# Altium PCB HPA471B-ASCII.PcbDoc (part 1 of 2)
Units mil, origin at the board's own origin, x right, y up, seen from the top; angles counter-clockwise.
Board outline 1305 x 1105 mil, 2 copper layers (Top Layer, Bottom Layer); 47 components, 32 nets, 115 pads, 21 vias.
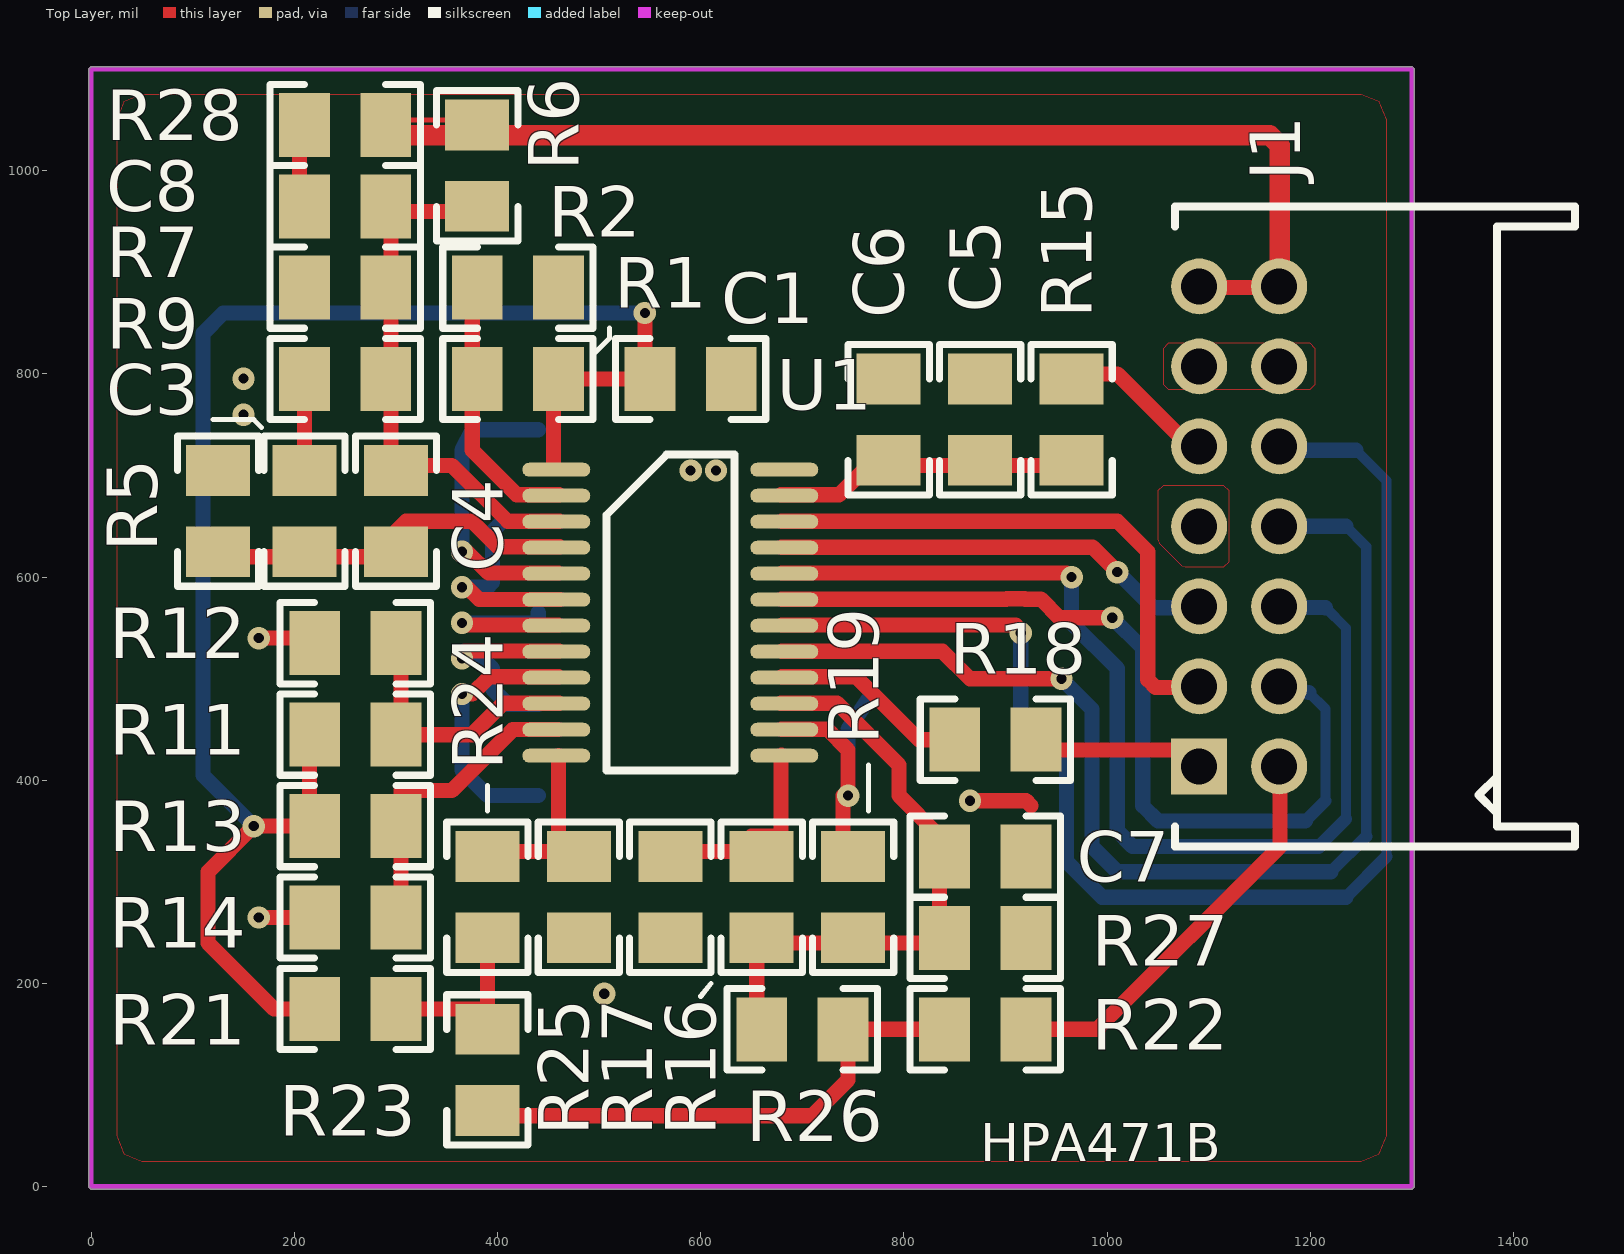
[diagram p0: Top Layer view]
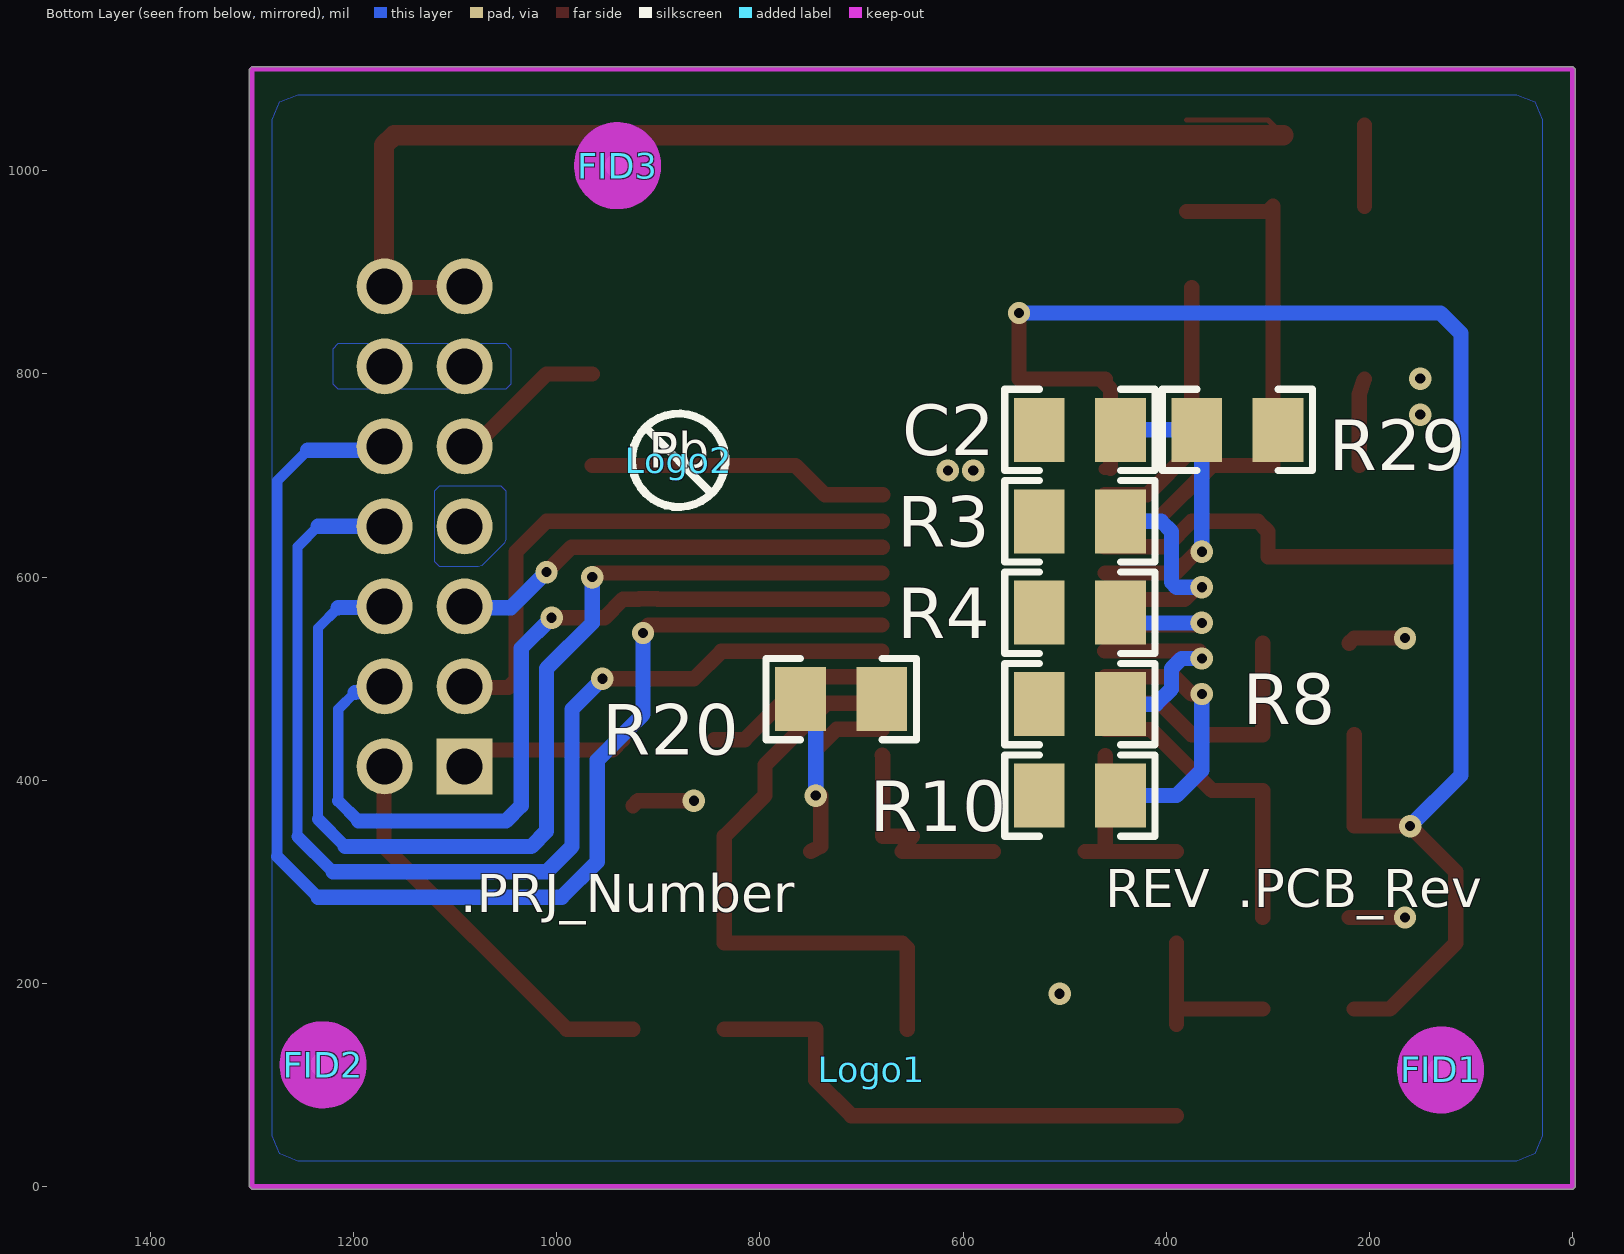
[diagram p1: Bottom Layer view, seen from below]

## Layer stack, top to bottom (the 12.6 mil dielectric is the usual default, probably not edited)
Top Layer: signal copper 2.8
Dielectric: core 12.6, FR-4, Dk 4.8
Bottom Layer: signal copper 2.8

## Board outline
-2.5,0 0,-2.5 1300,-2.5 1302.5,0 1302.5,1100 1300,1102.5 0,1102.5 -2.5,1100

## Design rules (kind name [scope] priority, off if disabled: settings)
AcuteAngle [All] p0: scope1count=1 scope1_0_kind=Board scope1_0_value=Board scope2count=1 scope2_0_kind=Board scope2_0_value=Board commentlength=0 minimum=4.50000000000000E+0001
AcuteAngle [All] p1: minimum=4.50000000000000E+0001 checktracksonly=TRUE
AssemblyTestPointUsage [All] p0: scope1count=1 scope1_0_kind=Board scope1_0_value=Board scope2count=1 scope2_0_kind=Board scope2_0_value=Board commentlength=0
AssemblyTestPointUsage [All] p1: valid=2
AssemblyTestpoint [All] p0: scope1count=1 scope1_0_kind=Board scope1_0_value=Board scope2count=1 scope2_0_kind=Board scope2_0_value=Board commentlength=0
Clearance Clearance_Poly [All] p0 off: scope1count=1 scope1_0_kind=Board scope1_0_value=Board scope2count=1 scope2_0_kind=Board scope2_0_value=Board commentlength=48 gap=12 // Protel DXP Scope 1 Expression Was: InPolygon
Clearance Clearance_BoardEdge_Poly [All] p0 off: scope1count=1 scope1_0_kind=Board scope1_0_value=Board scope2count=1 scope2_0_kind=Board scope2_0_value=Board commentlength=48 gap=19.68 // Protel DXP Scope 2 Expression Was: IsKeepOut
Clearance Clearance_BoardEdge [All] p0 off: scope1count=1 scope1_0_kind=Board scope1_0_value=Board scope2count=1 scope2_0_kind=Board scope2_0_value=Board commentlength=48 gap=19.68 // Protel DXP Scope 2 Expression Was: IsKeepout
Clearance Clearance_ALL [All] p0: scope1count=1 scope1_0_kind=Board scope1_0_value=Board scope2count=1 scope2_0_kind=Board scope2_0_value=Board commentlength=0 gap=8
Clearance Clearance_Poly [InPolygon] p1: gap=12
Clearance Clearance_BoardEdge_Poly [OnCopper and InPoly vs IsKeepOut] p2: gap=19.68
Clearance Clearance_BoardEdge [OnCopper and Not InComponentClass('Logo') and not InComponentClass('FiducialMark') and not InRegion(1000,500,4000,800) and Not IsKeepout vs IsKeepout] p3 off: gap=19.68
Clearance Clearance_ALL [All] p4: gap=8
ComponentClearance ComponentClearance_Logo [All] p0: scope1count=1 scope1_0_kind=ComponentClass scope1_0_value=Logo scope2count=1 scope2_0_kind=Board scope2_0_value=Board commentlength=0 gap=3.94 collisioncheckmode=3
ComponentClearance ComponentClearance_ScrewToNut [All] p0 off: scope1count=1 scope1_0_kind=Board scope1_0_value=Board scope2count=1 scope2_0_kind=Board scope2_0_value=Board commentlength=71 gap=0 collisioncheckmode=3 // Protel DXP Scope 2 Expression Was: (HasFootprint('Keystone_1902C'))
ComponentClearance ComponentClearance_MountingHoles [All] p0: scope1count=1 scope1_0_kind=ComponentClass scope1_0_value="Mounting Holes" scope2count=1 scope2_0_kind=Board scope2_0_value=Board commentlength=0 gap=19.68 collisioncheckmode=3
ComponentClearance ComponentClearance_SmallPassives [All] p0 off: scope1count=1 scope1_0_kind=Board scope1_0_value=Board scope2count=1 scope2_0_kind=Board scope2_0_value=Board commentlength=508 gap=7.87 collisioncheckmode=3 // Protel DXP Scope 2 Expression Was: HasFootprint('0201*') or HasFootprint('0402*') or HasFootprint('0508') or HasFootprint('0603*') or HasFootprint('0612') or HasFootprint('0805*') or HasFootprint('0815*') or HasFootprint('0830*') or HasFootprint('1206*') or HasFootprint('1210*') or HasFootprint('1808*') or HasFootprint('1812*') or HasFootprint('1825*') or HasFootprint('2010*') or HasFootprint('2220*') or HasFootprint('2225*') or HasFootprint('2512*') or HasFootprint('2728*') or HasFootprint('3518*')
ComponentClearance ComponentClearance_THtoSMT [All] p0 off: scope1count=1 scope1_0_kind=Board scope1_0_value=Board scope2count=1 scope2_0_kind=Board scope2_0_value=Board commentlength=53 gap=7.87 collisioncheckmode=3 // Protel DXP Scope 2 Expression Was: IsSMTComponent
ComponentClearance ComponentClearance_THtoTH [All] p0 off: scope1count=1 scope1_0_kind=Board scope1_0_value=Board scope2count=1 scope2_0_kind=Board scope2_0_value=Board commentlength=54 gap=7.87 collisioncheckmode=3 // Protel DXP Scope 2 Expression Was: IsThruComponent
ComponentClearance [All] p0: scope1count=1 scope1_0_kind=Board scope1_0_value=Board scope2count=1 scope2_0_kind=Board scope2_0_value=Board commentlength=0 gap=0 collisioncheckmode=3
ComponentClearance ComponentClearance_Logo [InComponentClass(Logo)] p1: gap=3.94 collisioncheckmode=3 verticalgap=27.56 showdistances=FALSE
ComponentClearance ComponentClearance_ScrewToNut [(HasFootprint('NY PMS 440 0025 PH')) vs (HasFootprint('Keystone_1902C'))] p2: gap=0 collisioncheckmode=3 verticalgap=0 showdistances=FALSE
ComponentClearance ComponentClearance_MountingHoles [InComponentClass('Mounting Holes')] p3: gap=19.68 collisioncheckmode=3 verticalgap=27.56 showdistances=FALSE
ComponentClearance ComponentClearance_SmallPassives [HasFootprint('0201*') or HasFootprint('0402*') or HasFootprint('0508') or HasFootprint('0603*') or HasFootprint('0612') or HasFootprint('0805*') or HasFootprint('0815*') or HasFootprint('0830*') or HasFootprint('1206*') or HasFootprint('1210*') or HasFootprint('1808*') or HasFootprint('1812*') or HasFootprint('1825*') or HasFootprint('2010*') or HasFootprint('2220*') or HasFootprint('2225*') or HasFootprint('2512*') or HasFootprint('2728*') or HasFootprint('3518*') vs HasFootprint('0201*') or HasFootprint('0402*') or HasFootprint('0508') or HasFootprint('0603*') or HasFootprint('0612') or HasFootprint('0805*') or HasFootprint('0815*') or HasFootprint('0830*') or HasFootprint('1206*') or HasFootprint('1210*') or HasFootprint('1808*') or HasFootprint('1812*') or HasFootprint('1825*') or HasFootprint('2010*') or HasFootprint('2220*') or HasFootprint('2225*') or HasFootprint('2512*') or HasFootprint('2728*') or HasFootprint('3518*')] p4: gap=7.87 collisioncheckmode=3 verticalgap=10 showdistances=FALSE
ComponentClearance ComponentClearance_THtoSMT [IsThruComponent vs IsSMTComponent] p5 off: gap=7.87 collisioncheckmode=3 verticalgap=27.56 showdistances=FALSE
ComponentClearance ComponentClearance_THtoTH [IsThruComponent vs IsThruComponent] p6 off: gap=7.87 collisioncheckmode=3 verticalgap=27.56 showdistances=FALSE
ComponentClearance [All] p7: gap=0 collisioncheckmode=3 verticalgap=0 showdistances=FALSE
DiffPairsRouting [All] p0: scope1count=1 scope1_0_kind=Board scope1_0_value=Board scope2count=1 scope2_0_kind=Board scope2_0_value=Board commentlength=0
DiffPairsRouting [All] p1: maxlimit=100 minlimit=10 mostfreqgap=10 maxuncoupledlength=1000
FabricationTestPointUsage TestPointUsage [All] p0: scope1count=1 scope1_0_kind=Board scope1_0_value=Board scope2count=1 scope2_0_kind=Board scope2_0_value=Board commentlength=0 valid=2 allowmultiple=FALSE
FabricationTestPointUsage TestPointUsage [All] p1: valid=2 allowmultiple=FALSE
FabricationTestpoint Testpoint [All] p0: scope1count=1 scope1_0_kind=Board scope1_0_value=Board scope2count=1 scope2_0_kind=Board scope2_0_value=Board commentlength=0 side=3 testpointundercomponent=TRUE minsize=40 maxsize=100 preferedsize=60 minholesize=0 maxholesize=40 preferedholesize=32 testpointgrid=1
FabricationTestpoint Testpoint [All] p1: side=3 testpointundercomponent=TRUE minsize=40 maxsize=100 preferedsize=60 minholesize=0 maxholesize=40 preferedholesize=32 testpointgrid=1 allowsidetop=TRUE allowsidebottom=TRUE usegrid=TRUE gridtolerance=0.01
FanoutControl Fanout_LCC [All] p0 off: scope1count=1 scope1_0_kind=Board scope1_0_value=Board scope2count=1 scope2_0_kind=Board scope2_0_value=Board commentlength=69 // Protel DXP Scope 1 Expression Was: IsLCC   Fanout_LCC (Default Rule)
FanoutControl Fanout_BGA [All] p0 off: scope1count=1 scope1_0_kind=Board scope1_0_value=Board scope2count=1 scope2_0_kind=Board scope2_0_value=Board commentlength=69 // Protel DXP Scope 1 Expression Was: IsBGA   Fanout_BGA (Default Rule)
FanoutControl Fanout_SOIC [All] p0 off: scope1count=1 scope1_0_kind=Board scope1_0_value=Board scope2count=1 scope2_0_kind=Board scope2_0_value=Board commentlength=71 // Protel DXP Scope 1 Expression Was: IsSOIC   Fanout_SOIC (Default Rule)
FanoutControl Fanout_Default [All] p0: scope1count=1 scope1_0_kind=Board scope1_0_value=Board scope2count=1 scope2_0_kind=Board scope2_0_value=Board commentlength=30 // Fanout_Default (Default Rule)
FanoutControl Fanout_Small [All] p0 off: scope1count=1 scope1_0_kind=Board scope1_0_value=Board scope2count=1 scope2_0_kind=Board scope2_0_value=Board commentlength=84 // Protel DXP Scope 1 Expression Was: (CompPinCount < 5)   Fanout_Small (Default Rule)
FanoutControl Fanout_LCC [IsLCC] p1: bgadir=Out bgaviamode=Centered fanoutstyle=Auto fanoutdirection=Alternating viagrid=1 // Fanout_LCC (Default Rule)
FanoutControl Fanout_BGA [IsBGA] p2: bgadir=Out bgaviamode=Centered fanoutstyle=Auto fanoutdirection=Alternating viagrid=1 // Fanout_BGA (Default Rule)
FanoutControl Fanout_Default [All] p4: bgadir=Out bgaviamode=Centered fanoutstyle=Auto fanoutdirection=Alternating viagrid=1 // Fanout_Default (Default Rule)
FanoutControl Fanout_Small [(CompPinCount < 5)] p5: bgadir=Out bgaviamode=Centered fanoutstyle=Auto fanoutdirection=OutThenIn viagrid=1 // Fanout_Small (Default Rule)
Height "Height Bottom" [All] p0 off: scope1count=1 scope1_0_kind=Board scope1_0_value=Board scope2count=1 scope2_0_kind=Board scope2_0_value=Board commentlength=64 // Protel DXP Scope 1 Expression Was: (OnLayer('Bottom Layer'))
Height Height_top [All] p0 off: scope1count=1 scope1_0_kind=Board scope1_0_value=Board scope2count=1 scope2_0_kind=Board scope2_0_value=Board commentlength=61 // Protel DXP Scope 1 Expression Was: (OnLayer('Top Layer'))
Height "Height Bottom" [(OnLayer('Bottom Layer'))] p1: minheight=0 maxheight=1000 prefheight=500
Height Height_top [(OnLayer('Top Layer'))] p2: minheight=0 maxheight=1750 prefheight=1750
HoleSize [All] p0: scope1count=1 scope1_0_kind=Board scope1_0_value=Board scope2count=1 scope2_0_kind=Board scope2_0_value=Board commentlength=0 absolutevalues=TRUE maxlimit=275.59 minlimit=8 maxpercent=80.000 minpercent=20.000
HoleSize [All] p1: absolutevalues=TRUE maxlimit=275.59 minlimit=8 maxpercent=80.000 minpercent=20.000
HoleToHoleClearance [All] p0: scope1count=1 scope1_0_kind=Board scope1_0_value=Board scope2count=1 scope2_0_kind=Board scope2_0_value=Board commentlength=0
LayerPairs [All] p0: scope1count=1 scope1_0_kind=Board scope1_0_value=Board scope2count=1 scope2_0_kind=Board scope2_0_value=Board commentlength=0 enforce=TRUE
MinimumAnnularRing [All] p0: scope1count=1 scope1_0_kind=Board scope1_0_value=Board scope2count=1 scope2_0_kind=Board scope2_0_value=Board commentlength=0 minimumring=6
MinimumAnnularRing [All] p1: minimumring=6
MinimumSolderMaskSliver MinimumSolderMaskSliver_Logo [All] p0: scope1count=1 scope1_0_kind=ComponentClass scope1_0_value=Logo scope2count=1 scope2_0_kind=ComponentClass scope2_0_value=Logo commentlength=0
MinimumSolderMaskSliver [All] p0: scope1count=1 scope1_0_kind=Board scope1_0_value=Board scope2count=1 scope2_0_kind=Board scope2_0_value=Board commentlength=0
MinimumSolderMaskSliver MinimumSolderMaskSliver_Logo [InComponentClass('Logo') vs InComponentClass('Logo')] p1: minsoldermaskwidth=0.7
MinimumSolderMaskSliver [All] p2: minsoldermaskwidth=4
NetAntennae [All] p0: scope1count=1 scope1_0_kind=Board scope1_0_value=Board scope2count=1 scope2_0_kind=Board scope2_0_value=Board commentlength=0
PasteMaskExpansion [All] p0: scope1count=1 scope1_0_kind=Board scope1_0_value=Board scope2count=1 scope2_0_kind=Board scope2_0_value=Board commentlength=0 expansion=0
PlaneClearance [All] p0: scope1count=1 scope1_0_kind=Board scope1_0_value=Board scope2count=1 scope2_0_kind=Board scope2_0_value=Board commentlength=0 clearance=20
PlaneConnect [All] p0: scope1count=1 scope1_0_kind=Board scope1_0_value=Board scope2count=1 scope2_0_kind=Board scope2_0_value=Board commentlength=0 planeconnectstyle=Relief reliefexpansion=10 reliefentries=4 reliefconductorwidth=10 reliefairgap=10
PlaneConnect [All] p1: planeconnectstyle=Relief reliefexpansion=10 reliefentries=4 reliefconductorwidth=10 reliefairgap=10
PolygonConnect PolygonConnect_23 [All] p0 off: scope1count=1 scope1_0_kind=Board scope1_0_value=Board scope2count=1 scope2_0_kind=Board scope2_0_value=Board commentlength=80 connectstyle=Direct reliefconductorwidth=10 reliefentries=4 polygonreliefangle="90 Angle" // Protel DXP Scope 2 Expression Was: IsNamedPolygon('Top Layer, Top-PWRGND 4')
PolygonConnect PolygonConnect_22 [All] p0 off: scope1count=1 scope1_0_kind=Board scope1_0_value=Board scope2count=1 scope2_0_kind=Board scope2_0_value=Board commentlength=80 connectstyle=Direct reliefconductorwidth=10 reliefentries=4 polygonreliefangle="90 Angle" // Protel DXP Scope 2 Expression Was: IsNamedPolygon('Top Layer, Top-PWRGND 4')
PolygonConnect PolygonConnect_21 [All] p0 off: scope1count=1 scope1_0_kind=Board scope1_0_value=Board scope2count=1 scope2_0_kind=Board scope2_0_value=Board commentlength=80 connectstyle=Direct reliefconductorwidth=10 reliefentries=4 polygonreliefangle="90 Angle" // Protel DXP Scope 2 Expression Was: IsNamedPolygon('Top Layer, Top-PWRGND 2')
PolygonConnect PolygonConnect_20 [All] p0 off: scope1count=1 scope1_0_kind=Board scope1_0_value=Board scope2count=1 scope2_0_kind=Board scope2_0_value=Board commentlength=80 connectstyle=Direct reliefconductorwidth=10 reliefentries=4 polygonreliefangle="90 Angle" // Protel DXP Scope 2 Expression Was: IsNamedPolygon('Top Layer, Top-PWRGND 3')
PolygonConnect PolygonConnect_19 [All] p0 off: scope1count=1 scope1_0_kind=Board scope1_0_value=Board scope2count=1 scope2_0_kind=Board scope2_0_value=Board commentlength=80 connectstyle=Direct reliefconductorwidth=10 reliefentries=4 polygonreliefangle="90 Angle" // Protel DXP Scope 2 Expression Was: IsNamedPolygon('Top Layer, Top-PWRGND 4')
PolygonConnect PolygonConnect_18 [All] p0 off: scope1count=1 scope1_0_kind=Board scope1_0_value=Board scope2count=1 scope2_0_kind=Board scope2_0_value=Board commentlength=75 connectstyle=Direct reliefconductorwidth=10 reliefentries=4 polygonreliefangle="90 Angle" // Protel DXP Scope 2 Expression Was: IsNamedPolygon('Top Layer, Top-GND')
PolygonConnect PolygonConnect_17 [All] p0 off: scope1count=1 scope1_0_kind=Board scope1_0_value=Board scope2count=1 scope2_0_kind=Board scope2_0_value=Board commentlength=77 connectstyle=Direct reliefconductorwidth=10 reliefentries=4 polygonreliefangle="90 Angle" // Protel DXP Scope 2 Expression Was: IsNamedPolygon('Top Layer, Top-GND 1')
PolygonConnect PolygonConnect_16 [All] p0 off: scope1count=1 scope1_0_kind=Board scope1_0_value=Board scope2count=1 scope2_0_kind=Board scope2_0_value=Board commentlength=77 connectstyle=Direct reliefconductorwidth=10 reliefentries=4 polygonreliefangle="90 Angle" // Protel DXP Scope 2 Expression Was: IsNamedPolygon('Top Layer, Top-GND 2')
PolygonConnect PolygonConnect_15 [All] p0 off: scope1count=1 scope1_0_kind=Board scope1_0_value=Board scope2count=1 scope2_0_kind=Board scope2_0_value=Board commentlength=80 connectstyle=Direct reliefconductorwidth=10 reliefentries=4 polygonreliefangle="90 Angle" // Protel DXP Scope 2 Expression Was: IsNamedPolygon('Top Layer, Top-NET00002')
PolygonConnect PolygonConnect_14 [All] p0 off: scope1count=1 scope1_0_kind=Board scope1_0_value=Board scope2count=1 scope2_0_kind=Board scope2_0_value=Board commentlength=80 connectstyle=Direct reliefconductorwidth=10 reliefentries=4 polygonreliefangle="90 Angle" // Protel DXP Scope 2 Expression Was: IsNamedPolygon('Top Layer, Top-NET00003')
PolygonConnect PolygonConnect_13 [All] p0 off: scope1count=1 scope1_0_kind=Board scope1_0_value=Board scope2count=1 scope2_0_kind=Board scope2_0_value=Board commentlength=80 connectstyle=Direct reliefconductorwidth=10 reliefentries=4 polygonreliefangle="90 Angle" // Protel DXP Scope 2 Expression Was: IsNamedPolygon('Top Layer, Top-NET00003')
PolygonConnect PolygonConnect_12 [All] p0 off: scope1count=1 scope1_0_kind=Board scope1_0_value=Board scope2count=1 scope2_0_kind=Board scope2_0_value=Board commentlength=80 connectstyle=Direct reliefconductorwidth=10 reliefentries=4 polygonreliefangle="90 Angle" // Protel DXP Scope 2 Expression Was: IsNamedPolygon('Top Layer, Top-NET00007')
PolygonConnect PolygonConnect_11 [All] p0 off: scope1count=1 scope1_0_kind=Board scope1_0_value=Board scope2count=1 scope2_0_kind=Board scope2_0_value=Board commentlength=80 connectstyle=Direct reliefconductorwidth=10 reliefentries=4 polygonreliefangle="90 Angle" // Protel DXP Scope 2 Expression Was: IsNamedPolygon('Top Layer, Top-NET00016')
PolygonConnect PolygonConnect_10 [All] p0 off: scope1count=1 scope1_0_kind=Board scope1_0_value=Board scope2count=1 scope2_0_kind=Board scope2_0_value=Board commentlength=80 connectstyle=Direct reliefconductorwidth=10 reliefentries=4 polygonreliefangle="90 Angle" // Protel DXP Scope 2 Expression Was: IsNamedPolygon('Top Layer, Top-NET00025')
PolygonConnect PolygonConnect_9 [All] p0 off: scope1count=1 scope1_0_kind=Board scope1_0_value=Board scope2count=1 scope2_0_kind=Board scope2_0_value=Board commentlength=82 connectstyle=Direct reliefconductorwidth=10 reliefentries=4 polygonreliefangle="90 Angle" // Protel DXP Scope 2 Expression Was: IsNamedPolygon('Top Layer, Top-NET00025 1')
PolygonConnect PolygonConnect_8 [All] p0 off: scope1count=1 scope1_0_kind=Board scope1_0_value=Board scope2count=1 scope2_0_kind=Board scope2_0_value=Board commentlength=78 connectstyle=Direct reliefconductorwidth=10 reliefentries=4 polygonreliefangle="90 Angle" // Protel DXP Scope 2 Expression Was: IsNamedPolygon('Top Layer, Top-No Net')
PolygonConnect PolygonConnect_7 [All] p0 off: scope1count=1 scope1_0_kind=Board scope1_0_value=Board scope2count=1 scope2_0_kind=Board scope2_0_value=Board commentlength=78 connectstyle=Direct reliefconductorwidth=10 reliefentries=4 polygonreliefangle="90 Angle" // Protel DXP Scope 2 Expression Was: IsNamedPolygon('Top Layer, Top-PWRGND')
PolygonConnect PolygonConnect_6 [All] p0 off: scope1count=1 scope1_0_kind=Board scope1_0_value=Board scope2count=1 scope2_0_kind=Board scope2_0_value=Board commentlength=80 connectstyle=Direct reliefconductorwidth=10 reliefentries=4 polygonreliefangle="90 Angle" // Protel DXP Scope 2 Expression Was: IsNamedPolygon('Top Layer, Top-PWRGND 1')
PolygonConnect PolygonConnect_5 [All] p0 off: scope1count=1 scope1_0_kind=Board scope1_0_value=Board scope2count=1 scope2_0_kind=Board scope2_0_value=Board commentlength=80 connectstyle=Direct reliefconductorwidth=10 reliefentries=4 polygonreliefangle="90 Angle" // Protel DXP Scope 2 Expression Was: IsNamedPolygon('Top Layer, Top-PWRGND 2')
PolygonConnect PolygonConnect_4 [All] p0 off: scope1count=1 scope1_0_kind=Board scope1_0_value=Board scope2count=1 scope2_0_kind=Board scope2_0_value=Board commentlength=80 connectstyle=Direct reliefconductorwidth=10 reliefentries=4 polygonreliefangle="90 Angle" // Protel DXP Scope 2 Expression Was: IsNamedPolygon('Top Layer, Top-PWRGND 3')
PolygonConnect PolygonConnect_3 [All] p0 off: scope1count=1 scope1_0_kind=Board scope1_0_value=Board scope2count=1 scope2_0_kind=Board scope2_0_value=Board commentlength=80 connectstyle=Direct reliefconductorwidth=10 reliefentries=4 polygonreliefangle="90 Angle" // Protel DXP Scope 2 Expression Was: IsNamedPolygon('Top Layer, Top-PWRGND 4')
PolygonConnect PolygonConnect_2 [All] p0 off: scope1count=1 scope1_0_kind=Board scope1_0_value=Board scope2count=1 scope2_0_kind=Board scope2_0_value=Board commentlength=126 connectstyle=Direct reliefconductorwidth=10 reliefentries=4 polygonreliefangle="90 Angle" // Protel DXP Scope 2 Expression Was: IsNamedPolygon('Top Layer, Top-PWRGND 3') Or  IsNamedPolygon('Top Layer, Top-PWRGND 4')
PolygonConnect PolygonConnect_1 [All] p0 off: scope1count=1 scope1_0_kind=Board scope1_0_value=Board scope2count=1 scope2_0_kind=Board scope2_0_value=Board commentlength=1642 connectstyle=Direct reliefconductorwidth=10 reliefentries=4 polygonreliefangle="90 Angle" // Protel DXP Scope 2 Expression Was: IsNamedPolygon('Top Layer, Top-PWRGND 2') Or  IsNamedPolygon('Bottom Layer, Bottom-GND') Or  IsNamedPolygon('Bottom Layer, Bottom-NET00038') Or  IsNamedPolygon('Bottom Layer, Bottom-NET00006') Or  IsNamedPolygon('Bottom Layer, Bottom-NET00003') Or  IsNamedPolygon('Bottom Layer, Bottom-NET00004 2') Or  IsNamedPolygon('Bottom Layer, Bottom-NET00020') Or  IsNamedPolygon('Bottom Layer, Bottom-GND 2') Or  IsNamedPolygon('Bottom Layer, Bottom-NET00004') Or  IsNamedPolygon('Bottom Layer, Bottom-PWRGND') Or  IsNamedPolygon('Bottom Layer, Bottom-NET00002 1') Or  IsNamedPolygon('Bottom Layer, Bottom-NET00013') Or  IsNamedPolygon('Bottom Layer, Bottom-NET00012') Or  IsNamedPolygon('Bottom Layer, Bottom-NET00004 3') Or  IsNamedPolygon('Bottom Layer, Bottom-NET00004 1') Or  IsNamedPolygon('Bottom Layer, Bottom-NET00016') Or  IsNamedPolygon('Bottom Layer, Bottom-GND 1') Or  IsNamedPolygon('Bottom Layer, Bottom-NET00025') Or  IsNamedPolygon('Bottom Layer, Bottom-NET00002') Or  IsNamedPolygon('Top Layer, Top-No Net') Or  IsNamedPolygon('Top Layer, Top-NET00016') Or  IsNamedPolygon('Top Layer, Top-NET00025 1') Or  IsNamedPolygon('Top Layer, Top-GND 2') Or  IsNamedPolygon('Top Layer, Top-PWRGND 3') Or  IsNamedPolygon('Top Layer, Top-PWRGND 4') Or  IsNamedPolygon('Top Layer, Top-NET00002') Or  IsNamedPolygon('Top Layer, Top-NET00007') Or  IsNamedPolygon('Top Layer, Top-GND 1') Or  IsNamedPolygon('Top Layer, Top-PWRGND 1') Or  IsNamedPolygon('Top Layer, Top-GND') Or  IsNamedPolygon('Top Layer, Top-NET00025') Or  IsNamedPolygon('Top Layer, Top-NET00003') Or  IsNamedPolygon('Top Layer, Top-PWRGND')
PolygonConnect [All] p0: scope1count=1 scope1_0_kind=Board scope1_0_value=Board scope2count=1 scope2_0_kind=Board scope2_0_value=Board commentlength=0 connectstyle=Relief reliefconductorwidth=10 reliefentries=4 polygonreliefangle="90 Angle"
PolygonConnect PolygonConnect_23 [All vs IsNamedPolygon('Top Layer, Top-PWRGND 4')] p1: connectstyle=Direct reliefconductorwidth=10 reliefentries=4 polygonreliefangle="90 Angle" airgapwidth=10
PolygonConnect PolygonConnect_22 [All vs IsNamedPolygon('Top Layer, Top-PWRGND 4')] p2: connectstyle=Direct reliefconductorwidth=10 reliefentries=4 polygonreliefangle="90 Angle" airgapwidth=10
PolygonConnect PolygonConnect_21 [All vs IsNamedPolygon('Top Layer, Top-PWRGND 2')] p3: connectstyle=Direct reliefconductorwidth=10 reliefentries=4 polygonreliefangle="90 Angle" airgapwidth=10
PolygonConnect PolygonConnect_20 [All vs IsNamedPolygon('Top Layer, Top-PWRGND 3')] p4: connectstyle=Direct reliefconductorwidth=10 reliefentries=4 polygonreliefangle="90 Angle" airgapwidth=10
PolygonConnect PolygonConnect_19 [All vs IsNamedPolygon('Top Layer, Top-PWRGND 4')] p5: connectstyle=Direct reliefconductorwidth=10 reliefentries=4 polygonreliefangle="90 Angle" airgapwidth=10
PolygonConnect PolygonConnect_18 [All vs IsNamedPolygon('Top Layer, Top-GND')] p6: connectstyle=Direct reliefconductorwidth=10 reliefentries=4 polygonreliefangle="90 Angle" airgapwidth=10
PolygonConnect PolygonConnect_17 [All vs IsNamedPolygon('Top Layer, Top-GND 1')] p7: connectstyle=Direct reliefconductorwidth=10 reliefentries=4 polygonreliefangle="90 Angle" airgapwidth=10
PolygonConnect PolygonConnect_16 [All vs IsNamedPolygon('Top Layer, Top-GND 2')] p8: connectstyle=Direct reliefconductorwidth=10 reliefentries=4 polygonreliefangle="90 Angle" airgapwidth=10
PolygonConnect PolygonConnect_15 [All vs IsNamedPolygon('Top Layer, Top-NET00002')] p9: connectstyle=Direct reliefconductorwidth=10 reliefentries=4 polygonreliefangle="90 Angle" airgapwidth=10
PolygonConnect PolygonConnect_14 [All vs IsNamedPolygon('Top Layer, Top-NET00003')] p10: connectstyle=Direct reliefconductorwidth=10 reliefentries=4 polygonreliefangle="90 Angle" airgapwidth=10
PolygonConnect PolygonConnect_13 [All vs IsNamedPolygon('Top Layer, Top-NET00003')] p11: connectstyle=Direct reliefconductorwidth=10 reliefentries=4 polygonreliefangle="90 Angle" airgapwidth=10
PolygonConnect PolygonConnect_12 [All vs IsNamedPolygon('Top Layer, Top-NET00007')] p12: connectstyle=Direct reliefconductorwidth=10 reliefentries=4 polygonreliefangle="90 Angle" airgapwidth=10
PolygonConnect PolygonConnect_11 [All vs IsNamedPolygon('Top Layer, Top-NET00016')] p13: connectstyle=Direct reliefconductorwidth=10 reliefentries=4 polygonreliefangle="90 Angle" airgapwidth=10
PolygonConnect PolygonConnect_10 [All vs IsNamedPolygon('Top Layer, Top-NET00025')] p14: connectstyle=Direct reliefconductorwidth=10 reliefentries=4 polygonreliefangle="90 Angle" airgapwidth=10
PolygonConnect PolygonConnect_9 [All vs IsNamedPolygon('Top Layer, Top-NET00025 1')] p15: connectstyle=Direct reliefconductorwidth=10 reliefentries=4 polygonreliefangle="90 Angle" airgapwidth=10
PolygonConnect PolygonConnect_8 [All vs IsNamedPolygon('Top Layer, Top-No Net')] p16: connectstyle=Direct reliefconductorwidth=10 reliefentries=4 polygonreliefangle="90 Angle" airgapwidth=10
PolygonConnect PolygonConnect_7 [All vs IsNamedPolygon('Top Layer, Top-PWRGND')] p17: connectstyle=Direct reliefconductorwidth=10 reliefentries=4 polygonreliefangle="90 Angle" airgapwidth=10
PolygonConnect PolygonConnect_6 [All vs IsNamedPolygon('Top Layer, Top-PWRGND 1')] p18: connectstyle=Direct reliefconductorwidth=10 reliefentries=4 polygonreliefangle="90 Angle" airgapwidth=10
PolygonConnect PolygonConnect_5 [All vs IsNamedPolygon('Top Layer, Top-PWRGND 2')] p19: connectstyle=Direct reliefconductorwidth=10 reliefentries=4 polygonreliefangle="90 Angle" airgapwidth=10
PolygonConnect PolygonConnect_4 [All vs IsNamedPolygon('Top Layer, Top-PWRGND 3')] p20: connectstyle=Direct reliefconductorwidth=10 reliefentries=4 polygonreliefangle="90 Angle" airgapwidth=10
PolygonConnect PolygonConnect_3 [All vs IsNamedPolygon('Top Layer, Top-PWRGND 4')] p21: connectstyle=Direct reliefconductorwidth=10 reliefentries=4 polygonreliefangle="90 Angle" airgapwidth=10
PolygonConnect PolygonConnect_2 [All vs IsNamedPolygon('Top Layer, Top-PWRGND 3') Or  IsNamedPolygon('Top Layer, Top-PWRGND 4')] p22: connectstyle=Direct reliefconductorwidth=10 reliefentries=4 polygonreliefangle="90 Angle" airgapwidth=10
PolygonConnect PolygonConnect_1 [All vs IsNamedPolygon('Top Layer, Top-PWRGND 2') Or  IsNamedPolygon('Bottom Layer, Bottom-GND') Or  IsNamedPolygon('Bottom Layer, Bottom-NET00038') Or  IsNamedPolygon('Bottom Layer, Bottom-NET00006') Or  IsNamedPolygon('Bottom Layer, Bottom-NET00003') Or  IsNamedPolygon('Bottom Layer, Bottom-NET00004 2') Or  IsNamedPolygon('Bottom Layer, Bottom-NET00020') Or  IsNamedPolygon('Bottom Layer, Bottom-GND 2') Or  IsNamedPolygon('Bottom Layer, Bottom-NET00004') Or  IsNamedPolygon('Bottom Layer, Bottom-PWRGND') Or  IsNamedPolygon('Bottom Layer, Bottom-NET00002 1') Or  IsNamedPolygon('Bottom Layer, Bottom-NET00013') Or  IsNamedPolygon('Bottom Layer, Bottom-NET00012') Or  IsNamedPolygon('Bottom Layer, Bottom-NET00004 3') Or  IsNamedPolygon('Bottom Layer, Bottom-NET00004 1') Or  IsNamedPolygon('Bottom Layer, Bottom-NET00016') Or  IsNamedPolygon('Bottom Layer, Bottom-GND 1') Or  IsNamedPolygon('Bottom Layer, Bottom-NET00025') Or  IsNamedPolygon('Bottom Layer, Bottom-NET00002') Or  IsNamedPolygon('Top Layer, Top-No Net') Or  IsNamedPolygon('Top Layer, Top-NET00016') Or  IsNamedPolygon('Top Layer, Top-NET00025 1') Or  IsNamedPolygon('Top Layer, Top-GND 2') Or  IsNamedPolygon('Top Layer, Top-PWRGND 3') Or  IsNamedPolygon('Top Layer, Top-PWRGND 4') Or  IsNamedPolygon('Top Layer, Top-NET00002') Or  IsNamedPolygon('Top Layer, Top-NET00007') Or  IsNamedPolygon('Top Layer, Top-GND 1') Or  IsNamedPolygon('Top Layer, Top-PWRGND 1') Or  IsNamedPolygon('Top Layer, Top-GND') Or  IsNamedPolygon('Top Layer, Top-NET00025') Or  IsNamedPolygon('Top Layer, Top-NET00003') Or  IsNamedPolygon('Top Layer, Top-PWRGND')] p23: connectstyle=Direct reliefconductorwidth=10 reliefentries=4 polygonreliefangle="90 Angle" airgapwidth=10
PolygonConnect [All] p24: connectstyle=Relief reliefconductorwidth=10 reliefentries=4 polygonreliefangle="90 Angle" airgapwidth=10
RoutingCorners [All] p0: scope1count=1 scope1_0_kind=Board scope1_0_value=Board scope2count=1 scope2_0_kind=Board scope2_0_value=Board commentlength=0 cornerstyle=45-Degree minsetback=100 maxsetback=100
RoutingLayers [All] p0: scope1count=1 scope1_0_kind=Board scope1_0_value=Board scope2count=1 scope2_0_kind=Board scope2_0_value=Board commentlength=0 top layer=Automatic bottom layer=Automatic
RoutingPriority [All] p0: scope1count=1 scope1_0_kind=Board scope1_0_value=Board scope2count=1 scope2_0_kind=Board scope2_0_value=Board commentlength=0
RoutingTopology [All] p0: scope1count=1 scope1_0_kind=Board scope1_0_value=Board scope2count=1 scope2_0_kind=Board scope2_0_value=Board commentlength=0 topology=Shortest
RoutingVias [All] p0: scope1count=1 scope1_0_kind=Board scope1_0_value=Board scope2count=1 scope2_0_kind=Board scope2_0_value=Board commentlength=0 holewidth=16 width=34 viastyle="Through Hole" minholewidth=6 minwidth=10 maxholewidth=40 maxwidth=65
RoutingVias [All] p1: holewidth=16 width=34 viastyle="Through Hole" minholewidth=6 minwidth=10 maxholewidth=40 maxwidth=65
SMDToCorner [All] p0 off: scope1count=1 scope1_0_kind=Board scope1_0_value=Board scope2count=1 scope2_0_kind=Board scope2_0_value=Board commentlength=0 distance=30000
SMDToCorner [All] p1 off: distance=30000
ShortCircuit [All] p0: scope1count=1 scope1_0_kind=Board scope1_0_value=Board scope2count=1 scope2_0_kind=Board scope2_0_value=Board commentlength=0 allowed=FALSE
SilkToSilkClearance [All] p0 off: scope1count=1 scope1_0_kind=Board scope1_0_value=Board scope2count=1 scope2_0_kind=Board scope2_0_value=Board commentlength=0
SilkToSilkClearance [All] p1 off: silktosilkclearance=4.5
SilkscreenOverComponentPads [All] p0 off: scope1count=1 scope1_0_kind=Board scope1_0_value=Board scope2count=1 scope2_0_kind=Board scope2_0_value=Board commentlength=0
SilkscreenOverComponentPads [All] p1 off: minsilkscreentomaskgap=5
SolderMaskExpansion [All] p0: scope1count=1 scope1_0_kind=Board scope1_0_value=Board scope2count=1 scope2_0_kind=Board scope2_0_value=Board commentlength=0 expansion=3
SolderMaskExpansion [All] p1: expansion=3
UnRoutedNet [All] p0: scope1count=1 scope1_0_kind=Board scope1_0_value=Board scope2count=1 scope2_0_kind=Board scope2_0_value=Board commentlength=0
Width [All] p0: scope1count=1 scope1_0_kind=Board scope1_0_value=Board scope2count=1 scope2_0_kind=Board scope2_0_value=Board commentlength=0 maxlimit=100 minlimit=10 preferedwidth=31.5
Width [All] p1: maxlimit=100 minlimit=10 preferedwidth=31.5 checkconnectedcopper=TRUE
13 further rules are at their usual default settings.

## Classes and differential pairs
component class HPA471B_Sht01: C1 C2 C3 C4 C5 C6 C7 C8 J1 R1 R2 R3 R4 R5 R6 R7 R8 R9 R10 R11 R12 R13 R14 R15 R16 R17 R18 R19 R20 R21 R22 R23 R24 R25 R26 R27 R28 R29 U1
component class HPA471B_Hardware: !PCB FID1 FID2 FID3 Logo1 Logo2 ZZ1 ZZ2 ZZ3

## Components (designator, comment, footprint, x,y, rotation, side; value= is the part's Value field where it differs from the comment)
C1 "08055C105KAT2A" 0805_HV 590,795 r180 top
C2 "C0805C154K5RACTU" 0805_HV 485,745 r180 bottom
C3 "08055C562KAT2A" 0805_HV 210,665 r90 top
C4 "08055C561KAT2A" 0805_HV 300,665 r90 top
C5 "08055C105KAT2A" 0805_HV 875,755 r270 top
C6 "08053C104KAT2A" 0805_HV 785,755 r270 top
C7 "08055C331KAT2A" 0805_HV 880,325 r180 top
C8 "08055C331KAT2A" 0805_HV 250,965 r180 top
FID1 "Fiducial" Fiducial6.4-20 130,115 r180 bottom
FID2 "Fiducial" Fiducial6.4-20 1230,120 r180 bottom
FID3 "Fiducial" Fiducial6.4-20 940,1005 r180 bottom
J1 "DF11-14DP-2DS(52)" Hirose_DF11-14DP-2DS_52 1130,650 r90 top
Logo1 "Texas Instruments" TI_Stacked_Overlay_Small 690,115 r180 bottom
Logo2 "Pb-Free Symbol" Pb-Free_Overlay_Small 880,715 r180 bottom
R1 "CRCW08052K37FKEA" 0805_HV 420,795 r0 top
R2 "CRCW08052K37FKEA" 0805_HV 420,885 r180 top
R3 "CRCW080512K1FKEA" 0805_HV 485,655 r180 bottom
R4 "CRCW080512K1FKEA" 0805_HV 485,565 r180 bottom
R5 "CRCW08051K00FKEA" 0805_HV 125,665 r90 top
R6 "CRCW08059K09FKEA" 0805_HV 380,1005 r90 top
R7 "CRCW08052K37FKEA" 0805_HV 250,885 r0 top
R8 "CRCW080556K2FKEA" 0805_HV 485,475 r180 bottom
R9 "CRCW080527K4FKEA" 0805_HV 250,795 r0 top
R10 "CRCW080513K3FKEA" 0805_HV 485,385 r180 bottom
R11 "CRCW080561K9FKEA" 0805_HV 260,445 r0 top
R12 "CRCW08051K00FKEA" 0805_HV 260,535 r0 top
R13 "CRCW08051K00FKEA" 0805_HV 260,355 r180 top
R14 "CRCW0805127KFKEA" 0805_HV 260,265 r0 top
R15 "CRCW080522R6FKEA" 0805_HV 965,755 r90 top
R16 "CRCW08051K00FKEA" 0805_HV 660,285 r270 top
R17 "CRCW08050000Z0EA" 0805_HV 570,285 r90 top
R18 "CRCW08051K00FKEA" 0805_HV 890,440 r0 top
R19 "CRCW08051K00FKEA" 0805_HV 750,285 r270 top
R20 "CRCW08050000Z0EA" 0805_HV 720,480 r0 bottom
R21 "CRCW08050000Z0EA" 0805_HV 260,175 r180 top
R22 "CRCW08051K00FKEA" 0805_HV 880,155 r0 top
R23 "CRCW08051K00FKEA" 0805_HV 390,115 r270 top
R24 "CRCW080516K9FKEA" 0805_HV 390,285 r270 top
R25 "CRCW08051K00FKEA" 0805_HV 480,285 r90 top
R26 "CRCW08050000Z0EA" 0805_HV 700,155 r0 top
R27 "CRCW08051K00FKEA" 0805_HV 880,245 r180 top
R28 "CRCW08051K00FKEA" 0805_HV 250,1045 r0 top
R29 "CRCW0805825KFKEA" 0805_HV 330,745 r0 bottom
U1 "UCC28950PW" PW0024A_N 570,565 r0 top
ZZ1 "These assemblies are ESD sensitive, ESD precautions shall be observed." AssemblyNote -120,6695 r0 top
ZZ2 "These assemblies must be clean and free from flux and all contaminants. Use of no clean flux is not acceptable." AssemblyNote -120,6590 r0 top
ZZ3 "These assemblies must comply with workmanship standards IPC-A-610 Class 2, unless otherwise specified." AssemblyNote -120,6470 r0 top

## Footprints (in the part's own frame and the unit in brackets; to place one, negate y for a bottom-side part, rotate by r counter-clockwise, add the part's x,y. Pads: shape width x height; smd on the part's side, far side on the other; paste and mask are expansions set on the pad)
0805_HV [mil] "0805 with 30mil clearance between pads"
  rect 50x63 smd: 1(-40,0) 2(40,0)
  silkscreen extent -74,-40 74,40
AssemblyNote [mil] "Assembly Note"
Fiducial6.4-20 [mil]
  round 25 smd mask+26.87: 1(0,0)
  Top Layer keep-out circle w46.37: c0,0 r19.68
Hirose_DF11-14DP-2DS_52 [mm] "TH, 14-Leads, Body 16x10mm, Pitch 2mm"
  rect 1.4x1.4 hole 0.9: 1(-6,1)
  round 1.4 hole 0.9: 2(-6,-1) 3(-4,1) 4(-4,-1) 5(-2,1) 6(-2,-1) 7(0,1) 8(0,-1) 9(2,1) 10(2,-1) 11(4,1) 12(4,-1) 13(6,1) 14(6,-1)
  silkscreen extent -8,-8.4 8,1.6
Pb-Free_Overlay_Small [mil]
  silkscreen extent -46,-46 46,46
PW0024A_N [mm] "TSOP, 24-Leads, Body 7.8x4.4mm, Pitch 0.65mm, IPC Medium Density"
  oval 1.7x0.35 smd: 1(-2.85,3.575) 2(-2.85,2.925) 3(-2.85,2.275) 4(-2.85,1.625) 5(-2.85,0.975) 6(-2.85,0.325) 7(-2.85,-0.325) 8(-2.85,-0.975) 9(-2.85,-1.625) 10(-2.85,-2.275) 11(-2.85,-2.925) 12(-2.85,-3.575) 13(2.85,-3.575) 14(2.85,-2.925) 15(2.85,-2.275) 16(2.85,-1.625) 17(2.85,-0.975) 18(2.85,-0.325) 19(2.85,0.325) 20(2.85,0.975) 21(2.85,1.625) 22(2.85,2.275) 23(2.85,2.925) 24(2.85,3.575)
  silkscreen extent -1.6,-3.95 1.6,3.95
TI_Stacked_Overlay_Small [mil]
